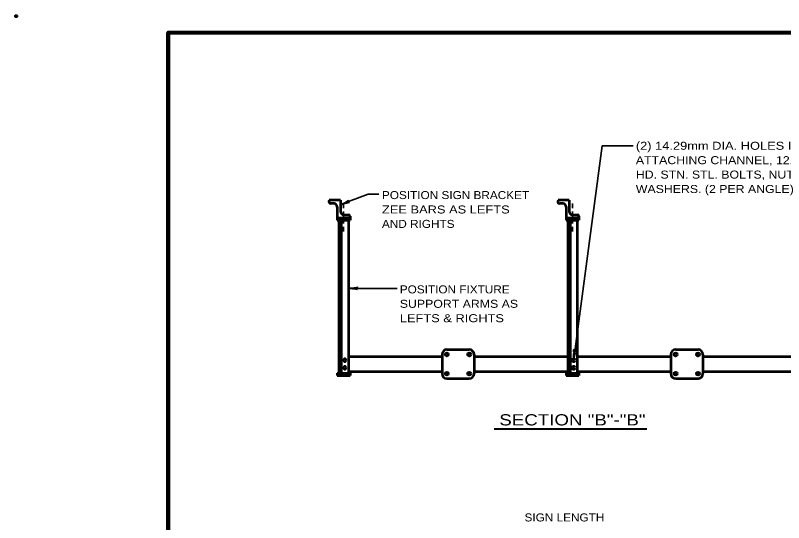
# Model space of a CAD drawing. Extents: x -94 to 762, y -50 to 494.
# Drawn here: x -93.6 to 194.5, y 303.7 to 493.8 of the extents above; entities that cross this region are included whole.
import ezdxf

# ---------------------------------------------------------------- set-up
doc = ezdxf.new("R2010")
doc.units = 0
doc.header["$LTSCALE"] = 1.2
doc.header["$PDMODE"] = 32
doc.header["$PDSIZE"] = 0.6
doc.layers.add('1', color=7, linetype='Continuous', lineweight=53)

msp = doc.modelspace()

# ---------------------------------------------------------------- linework, layer by layer
at = {"layer": '1'}
for p, q in [((28.279, 424.456), (24.079, 424.456)), ((28.279, 424.456), (28.279, 420.256)), ((114.079, 424.456), (109.879, 424.456)), ((114.079, 424.456), (114.079, 420.256)), ((25.879, 423.256), (24.679, 423.256)), ((27.079, 422.056), (27.079, 416.956)), ((111.679, 423.256), (110.479, 423.256)), ((112.879, 422.056), (112.879, 416.956)), ((27.079, 417.856), (31.879, 417.856)), ((29.479, 419.056), (31.279, 419.056)), ((31.879, 418.456), (31.879, 416.956)), ((112.879, 417.856), (117.679, 417.856)), ((115.279, 419.056), (117.079, 419.056)), ((117.679, 418.456), (117.679, 416.956)), ((27.079, 416.956), (31.879, 416.956)), ((27.679, 416.956), (27.679, 359.656)), ((28.579, 416.956), (28.579, 359.656)), ((112.879, 416.956), (117.679, 416.956)), ((113.479, 416.956), (113.479, 359.656)), ((114.379, 416.956), (114.379, 359.656)), ((117.079, 416.956), (117.079, 359.656)), ((31.279, 365.956), (66.379, 365.956)), ((66.379, 366.706), (66.379, 359.506)), ((68.179, 368.506), (76.579, 368.506)), ((78.379, 366.706), (78.379, 359.506)), ((78.379, 365.956), (113.479, 365.956)), ((117.079, 365.956), (152.179, 365.956)), ((152.179, 366.706), (152.179, 359.506)), ((153.979, 368.506), (162.379, 368.506)), ((164.179, 366.706), (164.179, 359.506)), ((164.179, 365.956), (199.279, 365.956)), ((31.279, 360.256), (66.379, 360.256)), ((78.379, 360.256), (113.479, 360.256)), ((117.079, 360.256), (152.179, 360.256)), ((164.179, 360.256), (199.279, 360.256)), ((27.079, 359.656), (27.079, 358.756)), ((27.079, 358.756), (31.879, 358.756)), ((31.879, 359.656), (31.879, 358.756)), ((68.179, 357.706), (76.579, 357.706)), ((112.879, 359.656), (112.879, 358.756)), ((112.879, 358.756), (117.679, 358.756)), ((117.679, 359.656), (117.679, 358.756)), ((153.979, 357.706), (162.379, 357.706))]:
    msp.add_line(p, q, dxfattribs=at)
at = {"layer": '1', "lineweight": 35}
for p, q in [((29.479, 423.256), (29.479, 421.456)), ((115.279, 423.256), (115.279, 421.456)), ((29.479, 420.256), (29.479, 415.756)), ((115.279, 420.256), (115.279, 415.756)), ((29.479, 414.556), (29.479, 412.756)), ((115.279, 414.556), (115.279, 412.756)), ((31.279, 391.456), (49.503, 391.456))]:
    msp.add_line(p, q, dxfattribs=at)
at = {"layer": '1', "lineweight": 40}
msp.add_line((85.961, 338.77), (143.16, 338.77), dxfattribs=at)
at = {"layer": '1', "lineweight": 158}
msp.add_lwpolyline([(755.402, 487.372), (-36.298, 487.272), (-36.198, -38.728)], dxfattribs=at)
at = {"layer": '1', "lineweight": 35}
for points in [[(115.729, 365.05), (126.402, 444.871), (138.058, 444.871)], [(28.328, 422.844), (38.695, 426.701), (42.638, 426.701)]]:
    msp.add_lwpolyline(points, dxfattribs=at)
at = {"layer": '1'}
for points in [[(31.279, 416.956), (31.279, 365.956), (31.279, 363.106), (31.279, 360.256), (31.279, 359.656)], [(27.079, 359.656), (28.579, 359.656), (31.279, 359.656), (31.879, 359.656)], [(112.879, 359.656), (114.379, 359.656), (117.679, 359.656)]]:
    msp.add_lwpolyline(points, dxfattribs=at)
for points in [[(30.529, 364.531), (30.229, 365.05), (29.629, 365.05), (29.329, 364.531), (29.629, 364.011), (30.229, 364.011)], [(116.329, 364.531), (116.029, 365.05), (115.429, 365.05), (115.129, 364.531), (115.429, 364.011), (116.029, 364.011)], [(30.529, 361.681), (30.229, 362.201), (29.629, 362.201), (29.329, 361.681), (29.629, 361.161), (30.229, 361.161)], [(116.329, 361.681), (116.029, 362.201), (115.429, 362.201), (115.129, 361.681), (115.429, 361.161), (116.029, 361.161)]]:
    msp.add_lwpolyline(points, close=True, dxfattribs=at)
for centre in [(68.179, 366.706), (76.579, 366.706), (153.979, 366.706), (162.379, 366.706), (68.179, 359.506), (76.579, 359.506), (153.979, 359.506), (162.379, 359.506)]:
    msp.add_circle(centre, 0.6, dxfattribs=at)
for centre, radius, start, end in [((24.684, 424.008), 0.752, 143.49847, 269.63162), ((110.484, 424.008), 0.752, 143.49847, 269.63162), ((25.879, 422.056), 1.2, 0, 90), ((111.679, 422.056), 1.2, 0, 90), ((29.479, 420.256), 1.2, 180, 270), ((31.279, 418.456), 0.6, 0, 90), ((115.279, 420.256), 1.2, 180, 270), ((117.079, 418.456), 0.6, 0, 90), ((68.179, 366.706), 1.8, 90, 180), ((76.579, 366.706), 1.8, 0, 90), ((153.979, 366.706), 1.8, 90, 180), ((162.379, 366.706), 1.8, 0, 90), ((68.179, 359.506), 1.8, 180, 270), ((76.579, 359.506), 1.8, 270, 0), ((153.979, 359.506), 1.8, 180, 270), ((162.379, 359.506), 1.8, 270, 0)]:
    msp.add_arc(centre, radius, start, end, dxfattribs=at)
at = {"layer": '1', "lineweight": 40}
for centre, major_axis, ratio, start_param, end_param in [((29.44, 423.611), (-1.943, -0.923), 0.122415, 0.8963533, 3.1415927), ((29.44, 423.611), (-1.943, -0.923), 0.122415, 0.8963533, 3.1415927), ((29.677, 423.075), (-2.049, -0.537), 0.07063, 3.1407148, 5.41811), ((29.677, 423.075), (-2.049, -0.537), 0.07063, 3.1407148, 5.41811), ((32.589, 391.787), (-2.143, -0.187), 0.122415, 0.8963533, 3.1415927), ((32.624, 391.202), (-2.108, 0.211), 0.07063, 3.1407148, 5.41811), ((115.574, 366.392), (-0.098, -2.149), 0.122415, 0.8963533, 3.1415927), ((116.159, 366.35), (0.488, 2.061), 0.07063, 6.2823074, 8.5597026)]:
    msp.add_ellipse(centre, major_axis=major_axis, ratio=ratio, start_param=start_param, end_param=end_param, dxfattribs=at)
at = {"layer": '1'}
msp.add_point((-93.298, 493.472), dxfattribs=at)

# ---------------------------------------------------------------- texts
for s, height, width, p in [('(2) 14.29mm DIA. HOLES IN ANGLE FOR', 3, 1.2, (139.041, 443.399)), ('ATTACHING CHANNEL, 12.7mm DIA. HEX.', 3, 1.15, (139.041, 437.999)), ('HD. STN. STL. BOLTS, NUTS AND', 3, 1.15, (139.041, 432.599)), ('WASHERS. (2 PER ANGLE)', 3, 1.15, (139.041, 427.199)), ('POSITION SIGN BRACKET', 3, 1.1, (43.853, 424.92)), ('ZEE BARS AS LEFTS', 3, 1.2, (43.853, 419.52)), ('AND RIGHTS', 3, 1.1, (43.853, 414.12)), ('POSITION FIXTURE', 3, 1.1, (50.538, 389.571)), ('SUPPORT ARMS AS', 3, 1.15, (50.538, 384.171)), ('LEFTS & RIGHTS', 3, 1.2, (50.538, 378.771)), ('SECTION "B"-"B"', 4.2, 1.25, (87.838, 340.084)), ('SIGN LENGTH', 3, 1.1, (97.302, 304.097))]:
    msp.add_text(s, height=height, dxfattribs=dict(at, width=width)).set_placement(p)

doc.saveas('drawing.dxf')
